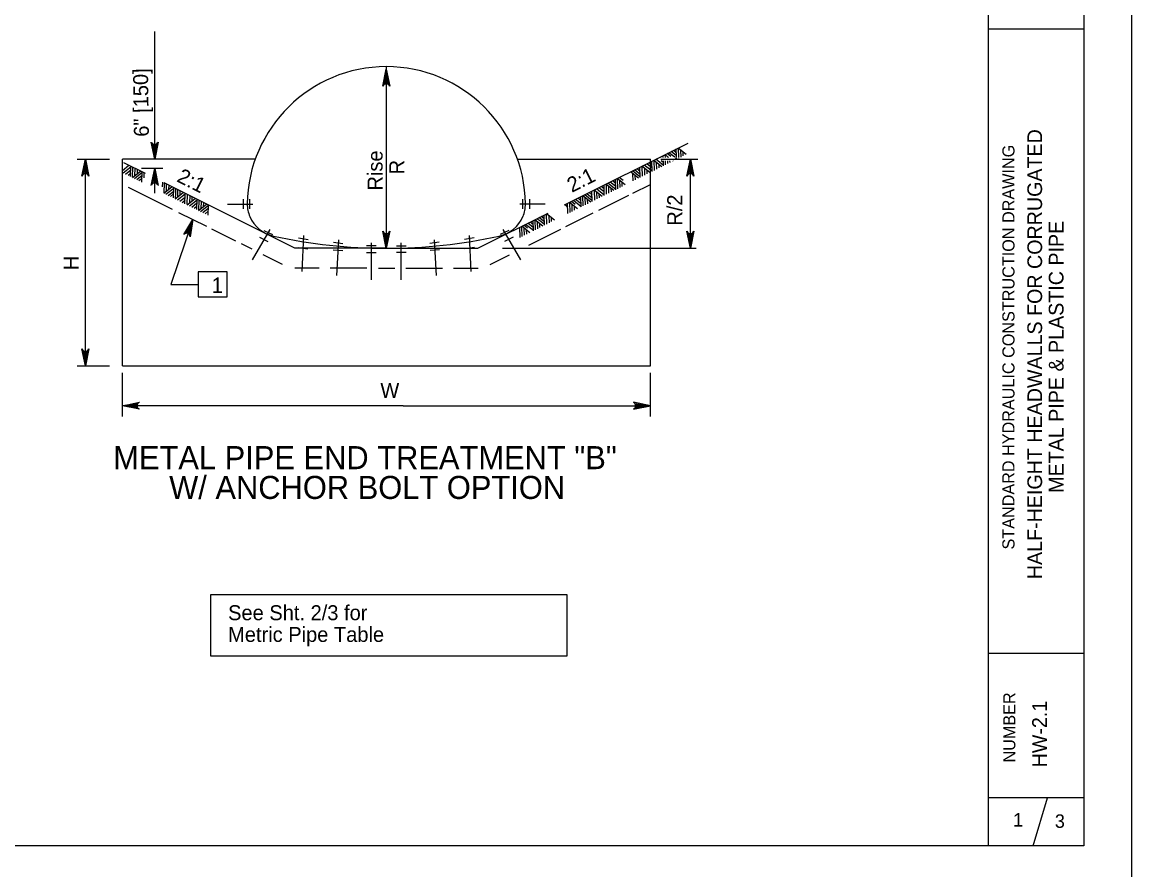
# Model space of a CAD drawing. Extents: x 1083.1 to 1117.1, y 675.4 to 741.4.
# Drawn here: x 1105.58 to 1117.13, y 719.6 to 728.43 of the extents above; entities that cross this region are included whole.
import ezdxf

# ---------------------------------------------------------------- set-up
doc = ezdxf.new("R2010")
doc.units = 0
doc.layers.add('Level 1', color=7, linetype='Continuous')

msp = doc.modelspace()

# ---------------------------------------------------------------- linework, layer by layer
at = {"layer": 'Level 1'}
for p, q in [((1115.636, 719.854), (1115.636, 740.854)), ((1106.962, 727.001), (1106.962, 728.328)), ((1116.626, 728.354), (1115.636, 728.354)), ((1109.347, 727.775), (1109.371, 727.937)), ((1109.357, 727.781), (1109.371, 727.937)), ((1109.371, 727.964), (1109.371, 726.643)), ((1109.371, 727.784), (1109.371, 727.937)), ((1109.383, 727.782), (1109.371, 727.937)), ((1109.394, 727.777), (1109.371, 727.937)), ((1106.939, 727.161), (1106.962, 727.001)), ((1106.95, 727.156), (1106.962, 727.001)), ((1106.987, 727.163), (1106.962, 727.001)), ((1106.976, 727.157), (1106.962, 727.001)), ((1106.962, 727.154), (1106.962, 727.001)), ((1111.223, 726.524), (1112.512, 727.168)), ((1112.229, 727.017), (1112.222, 727.023)), ((1112.252, 727.017), (1112.251, 727.038)), ((1112.307, 727.019), (1112.271, 727.048)), ((1112.274, 727.018), (1112.273, 727.045)), ((1112.331, 727.027), (1112.292, 727.058)), ((1112.298, 727.018), (1112.297, 727.026)), ((1112.371, 727.02), (1112.311, 727.067)), ((1112.391, 727.034), (1112.334, 727.079)), ((1112.39, 727.066), (1112.359, 727.091)), ((1112.392, 727.003), (1112.378, 727.014)), ((1112.391, 727.02), (1112.388, 727.107)), ((1112.392, 727), (1112.391, 727.015)), ((1112.491, 727.049), (1112.408, 727.116)), ((1112.413, 727.02), (1112.41, 727.114)), ((1112.413, 727.01), (1112.413, 727.016)), ((1112.437, 727.022), (1112.434, 727.095)), ((1112.46, 727.034), (1112.458, 727.076)), ((1106.154, 727.001), (1106.493, 727.001)), ((1106.215, 726.839), (1106.24, 727.001)), ((1106.226, 726.845), (1106.24, 727.001)), ((1106.24, 725.784), (1106.24, 727.001)), ((1106.24, 726.848), (1106.24, 727.001)), ((1106.251, 726.846), (1106.24, 727.001)), ((1106.262, 726.841), (1106.24, 727.001)), ((1106.625, 724.848), (1106.625, 727.001)), ((1108.008, 727.001), (1106.625, 727.001)), ((1106.625, 726.881), (1106.694, 726.937)), ((1106.634, 726.858), (1106.714, 726.921)), ((1106.866, 726.851), (1106.641, 726.963)), ((1106.659, 726.846), (1106.713, 726.889)), ((1106.711, 726.82), (1106.714, 726.926)), ((1106.732, 726.812), (1106.735, 726.916)), ((1106.756, 726.832), (1106.758, 726.904)), ((1106.781, 726.852), (1106.783, 726.892)), ((1107.045, 726.905), (1106.823, 726.905)), ((1106.937, 726.743), (1106.962, 726.905)), ((1106.947, 726.749), (1106.962, 726.905)), ((1106.962, 726.647), (1106.962, 726.905)), ((1106.962, 726.752), (1106.962, 726.905)), ((1106.973, 726.75), (1106.962, 726.905)), ((1106.984, 726.745), (1106.962, 726.905)), ((1110.735, 727.001), (1112.118, 727.001)), ((1112.01, 726.844), (1111.954, 726.889)), ((1112.009, 726.875), (1111.977, 726.901)), ((1112.011, 726.809), (1112.007, 726.916)), ((1112.113, 726.861), (1112.03, 726.927)), ((1112.036, 726.822), (1112.034, 726.924)), ((1112.136, 726.875), (1112.055, 726.939)), ((1112.061, 726.834), (1112.059, 726.904)), ((1112.135, 726.908), (1112.08, 726.952)), ((1112.133, 726.939), (1112.103, 726.963)), ((1112.118, 724.848), (1112.118, 727.001)), ((1112.136, 726.872), (1112.133, 726.978)), ((1112.236, 726.922), (1112.153, 726.988)), ((1112.16, 726.884), (1112.157, 726.985)), ((1112.194, 726.983), (1112.174, 726.999)), ((1112.185, 726.896), (1112.182, 726.965)), ((1112.255, 726.935), (1112.195, 726.982)), ((1112.21, 726.909), (1112.208, 726.944)), ((1112.226, 727.001), (1112.612, 727.001)), ((1112.254, 726.965), (1112.23, 726.984)), ((1112.255, 726.931), (1112.253, 726.984)), ((1112.276, 726.942), (1112.275, 726.983)), ((1112.3, 726.954), (1112.299, 726.983)), ((1112.323, 726.965), (1112.322, 726.983)), ((1112.354, 726.981), (1112.352, 726.982)), ((1112.509, 726.839), (1112.534, 727.001)), ((1112.519, 726.845), (1112.534, 727.001)), ((1112.534, 726.373), (1112.534, 727.001)), ((1112.534, 726.848), (1112.534, 727.001)), ((1112.545, 726.846), (1112.534, 727.001)), ((1112.556, 726.841), (1112.534, 727.001)), ((1106.684, 726.833), (1106.712, 726.856)), ((1106.729, 726.811), (1106.813, 726.877)), ((1106.751, 726.8), (1106.832, 726.864)), ((1106.775, 726.788), (1106.831, 726.833)), ((1106.797, 726.777), (1106.83, 726.803)), ((1106.829, 726.761), (1106.832, 726.867)), ((1106.852, 726.807), (1106.853, 726.857)), ((1111.756, 726.749), (1111.724, 726.774)), ((1111.758, 726.683), (1111.754, 726.79)), ((1111.857, 726.732), (1111.774, 726.799)), ((1111.779, 726.693), (1111.776, 726.797)), ((1111.834, 726.779), (1111.795, 726.81)), ((1111.803, 726.705), (1111.8, 726.778)), ((1111.994, 726.801), (1111.911, 726.867)), ((1111.971, 726.847), (1111.932, 726.878)), ((1111.94, 726.774), (1111.937, 726.846)), ((1111.963, 726.785), (1111.961, 726.827)), ((1112.01, 726.816), (1111.971, 726.847)), ((1112.086, 726.847), (1112.084, 726.883)), ((1107.147, 726.477), (1106.689, 726.706)), ((1107.043, 726.712), (1107.045, 726.761)), ((1107.057, 726.647), (1107.141, 726.713)), ((1108.42, 726.073), (1107.06, 726.753)), ((1107.06, 726.649), (1107.063, 726.752)), ((1107.079, 726.636), (1107.159, 726.7)), ((1107.084, 726.668), (1107.086, 726.74)), ((1107.103, 726.624), (1107.159, 726.669)), ((1107.109, 726.688), (1107.111, 726.728)), ((1107.157, 726.597), (1107.16, 726.703)), ((1107.18, 726.643), (1107.182, 726.693)), ((1107.201, 726.61), (1107.203, 726.682)), ((1107.225, 726.63), (1107.226, 726.67)), ((1111.514, 726.561), (1111.51, 726.667)), ((1111.616, 726.612), (1111.533, 726.678)), ((1111.539, 726.574), (1111.537, 726.675)), ((1111.639, 726.626), (1111.558, 726.691)), ((1111.638, 726.659), (1111.583, 726.703)), ((1111.636, 726.69), (1111.606, 726.715)), ((1111.639, 726.623), (1111.636, 726.73)), ((1111.739, 726.674), (1111.656, 726.74)), ((1111.663, 726.635), (1111.66, 726.737)), ((1111.758, 726.686), (1111.677, 726.75)), ((1111.687, 726.648), (1111.685, 726.717)), ((1111.757, 726.717), (1111.7, 726.762)), ((1111.713, 726.66), (1111.711, 726.696)), ((1111.826, 726.717), (1111.824, 726.759)), ((1111.935, 726.646), (1112.118, 726.738)), ((1107.125, 726.613), (1107.158, 726.639)), ((1107.173, 726.589), (1107.257, 726.655)), ((1107.179, 726.593), (1107.18, 726.643)), ((1107.199, 726.576), (1107.279, 726.639)), ((1107.224, 726.563), (1107.278, 726.606)), ((1107.248, 726.551), (1107.277, 726.574)), ((1107.276, 726.537), (1107.279, 726.644)), ((1107.299, 726.526), (1107.382, 726.592)), ((1107.301, 726.528), (1107.304, 726.631)), ((1107.322, 726.514), (1107.402, 726.577)), ((1107.327, 726.548), (1107.329, 726.619)), ((1107.347, 726.502), (1107.401, 726.545)), ((1107.351, 726.568), (1107.352, 726.607)), ((1107.399, 726.476), (1107.402, 726.582)), ((1107.42, 726.468), (1107.423, 726.572)), ((1107.444, 726.488), (1107.447, 726.56)), ((1107.469, 726.508), (1107.471, 726.548)), ((1107.882, 726.583), (1107.882, 726.483)), ((1107.951, 726.483), (1107.951, 726.583)), ((1109.371, 726.653), (1109.371, 726.073)), ((1110.792, 726.483), (1110.792, 726.583)), ((1110.861, 726.583), (1110.861, 726.483)), ((1111.261, 726.434), (1111.257, 726.541)), ((1111.36, 726.484), (1111.277, 726.55)), ((1111.282, 726.445), (1111.279, 726.548)), ((1111.337, 726.53), (1111.298, 726.561)), ((1111.398, 726.506), (1111.317, 726.57)), ((1111.397, 726.537), (1111.34, 726.582)), ((1111.396, 726.569), (1111.364, 726.594)), ((1111.398, 726.503), (1111.394, 726.61)), ((1111.497, 726.552), (1111.414, 726.619)), ((1111.419, 726.514), (1111.416, 726.617)), ((1111.474, 726.599), (1111.435, 726.63)), ((1111.443, 726.525), (1111.44, 726.597)), ((1111.513, 726.596), (1111.456, 726.64)), ((1111.466, 726.537), (1111.464, 726.579)), ((1111.513, 726.567), (1111.474, 726.599)), ((1111.512, 726.627), (1111.48, 726.652)), ((1111.564, 726.586), (1111.562, 726.655)), ((1111.582, 726.47), (1111.893, 726.625)), ((1111.589, 726.598), (1111.587, 726.635)), ((1107.503, 726.299), (1107.214, 726.443)), ((1107.372, 726.489), (1107.4, 726.511)), ((1107.418, 726.466), (1107.501, 726.533)), ((1107.439, 726.456), (1107.52, 726.52)), ((1107.463, 726.444), (1107.519, 726.489)), ((1107.486, 726.433), (1107.518, 726.459)), ((1107.517, 726.417), (1107.52, 726.523)), ((1107.718, 726.533), (1107.982, 726.533)), ((1110.323, 726.073), (1111.056, 726.44)), ((1111.025, 726.533), (1110.76, 726.533)), ((1111.119, 726.364), (1111.036, 726.43)), ((1111.042, 726.325), (1111.039, 726.427)), ((1111.259, 726.501), (1111.227, 726.526)), ((1111.239, 726.299), (1111.523, 726.441)), ((1111.306, 726.457), (1111.303, 726.529)), ((1111.329, 726.468), (1111.327, 726.51)), ((1107.28, 726.227), (1107.359, 726.371)), ((1107.292, 726.229), (1107.359, 726.371)), ((1107.307, 726.227), (1107.359, 726.371)), ((1107.317, 726.222), (1107.359, 726.371)), ((1107.325, 726.213), (1107.359, 726.371)), ((1110.84, 726.282), (1110.801, 726.313)), ((1110.901, 726.258), (1110.82, 726.322)), ((1110.9, 726.288), (1110.843, 726.334)), ((1110.899, 726.32), (1110.867, 726.346)), ((1110.901, 726.254), (1110.897, 726.361)), ((1111, 726.304), (1110.917, 726.37)), ((1110.922, 726.265), (1110.919, 726.368)), ((1110.977, 726.35), (1110.938, 726.381)), ((1110.946, 726.277), (1110.943, 726.349)), ((1111.015, 726.347), (1110.959, 726.392)), ((1110.968, 726.288), (1110.967, 726.33)), ((1111.016, 726.319), (1110.977, 726.35)), ((1111.014, 726.378), (1110.983, 726.404)), ((1111.016, 726.312), (1111.013, 726.419)), ((1111.067, 726.337), (1111.065, 726.407)), ((1111.091, 726.35), (1111.09, 726.386)), ((1112.534, 726.073), (1112.534, 726.373)), ((1107.807, 726.147), (1107.556, 726.272)), ((1108.16, 726.269), (1107.976, 725.952)), ((1108.096, 726.257), (1108.188, 726.217)), ((1108.51, 726.206), (1108.492, 725.833)), ((1109.349, 726.234), (1109.371, 726.073)), ((1109.36, 726.228), (1109.371, 726.073)), ((1109.396, 726.236), (1109.371, 726.073)), ((1109.386, 726.23), (1109.371, 726.073)), ((1109.371, 726.227), (1109.371, 726.073)), ((1110.233, 726.206), (1110.251, 725.833)), ((1110.646, 726.257), (1110.555, 726.217)), ((1110.583, 726.269), (1110.767, 725.952)), ((1110.764, 726.186), (1110.76, 726.293)), ((1110.863, 726.235), (1110.78, 726.302)), ((1110.785, 726.197), (1110.782, 726.3)), ((1110.809, 726.208), (1110.806, 726.281)), ((1110.832, 726.22), (1110.83, 726.262)), ((1110.855, 726.107), (1111.187, 726.272)), ((1112.512, 726.234), (1112.534, 726.073)), ((1112.523, 726.228), (1112.534, 726.073)), ((1112.559, 726.236), (1112.534, 726.073)), ((1112.548, 726.23), (1112.534, 726.073)), ((1112.534, 726.227), (1112.534, 726.073)), ((1107.976, 726.063), (1107.863, 726.119)), ((1108.051, 726.188), (1108.14, 726.144)), ((1108.455, 726.081), (1108.554, 726.066)), ((1108.459, 726.182), (1108.557, 726.166)), ((1108.822, 726.138), (1108.92, 726.122)), ((1108.872, 726.162), (1108.854, 725.789)), ((1109.266, 726.098), (1109.166, 726.098)), ((1109.216, 725.745), (1109.216, 726.13)), ((1109.477, 726.098), (1109.577, 726.098)), ((1109.527, 725.745), (1109.527, 726.13)), ((1109.921, 726.138), (1109.823, 726.122)), ((1109.87, 726.162), (1109.888, 725.789)), ((1110.284, 726.182), (1110.185, 726.166)), ((1110.288, 726.081), (1110.189, 726.066)), ((1110.692, 726.188), (1110.602, 726.144)), ((1108.291, 725.905), (1108.089, 726.006)), ((1109.378, 726.073), (1108.42, 726.073)), ((1108.817, 726.058), (1108.917, 726.051)), ((1109.166, 726.029), (1109.266, 726.029)), ((1109.378, 726.073), (1110.323, 726.073)), ((1109.577, 726.029), (1109.477, 726.029)), ((1109.926, 726.058), (1109.826, 726.051)), ((1110.452, 725.905), (1110.654, 726.006)), ((1110.581, 726.073), (1112.593, 726.073)), ((1108.674, 725.865), (1108.418, 725.865)), ((1109.168, 725.865), (1108.788, 725.865)), ((1109.29, 725.865), (1109.458, 725.865)), ((1109.575, 725.865), (1109.954, 725.865)), ((1110.069, 725.865), (1110.325, 725.865)), ((1106.24, 724.848), (1106.24, 725.784)), ((1107.415, 725.828), (1107.415, 725.567)), ((1107.714, 725.828), (1107.415, 725.828)), ((1107.714, 725.567), (1107.714, 725.828)), ((1107.415, 725.567), (1107.714, 725.567)), ((1115.868, 725.06), (1115.868, 725.06)), ((1116.258, 725.067), (1116.258, 725.067)), ((1106.218, 725.009), (1106.24, 724.848)), ((1106.229, 725.003), (1106.24, 724.848)), ((1106.265, 725.011), (1106.24, 724.848)), ((1106.254, 725.005), (1106.24, 724.848)), ((1106.24, 725.002), (1106.24, 724.848)), ((1106.154, 724.848), (1106.493, 724.848)), ((1106.625, 724.848), (1112.118, 724.848)), ((1106.622, 724.778), (1106.622, 724.323)), ((1112.115, 724.778), (1112.115, 724.323)), ((1106.785, 724.457), (1106.625, 724.434)), ((1106.779, 724.446), (1106.625, 724.434)), ((1109.547, 724.434), (1106.625, 724.434)), ((1106.778, 724.434), (1106.625, 724.434)), ((1106.781, 724.42), (1106.625, 724.434)), ((1106.787, 724.41), (1106.625, 724.434)), ((1109.547, 724.434), (1112.118, 724.434)), ((1111.956, 724.41), (1112.118, 724.434)), ((1111.958, 724.457), (1112.118, 724.434)), ((1111.962, 724.42), (1112.118, 724.434)), ((1111.963, 724.446), (1112.118, 724.434)), ((1111.965, 724.434), (1112.118, 724.434)), ((1107.544, 722.47), (1111.249, 722.47)), ((1107.544, 721.828), (1107.544, 722.47)), ((1111.249, 722.47), (1111.249, 721.828)), ((1111.249, 721.828), (1107.544, 721.828)), ((1116.626, 721.854), (1115.636, 721.854)), ((1116.626, 720.354), (1115.636, 720.354)), ((1116.101, 719.854), (1116.251, 720.354))]:
    msp.add_line(p, q, dxfattribs=at)
for points in [[(1083.126, 719.354), (1117.126, 719.354), (1117.126, 741.354), (1083.126, 741.354)], [(1085.126, 740.854), (1116.626, 740.854), (1116.626, 719.854), (1085.126, 719.854)]]:
    msp.add_lwpolyline(points, close=True, dxfattribs=at)
for points in [[(1109.336, 727.76), (1109.371, 727.937), (1109.407, 727.76)], [(1106.997, 727.178), (1106.962, 727.001), (1106.926, 727.178)], [(1106.205, 726.824), (1106.24, 727.001), (1106.275, 726.824)], [(1106.926, 726.728), (1106.962, 726.905), (1106.997, 726.728)], [(1112.498, 726.824), (1112.534, 727.001), (1112.569, 726.824)], [(1107.359, 726.371), (1107.131, 725.697), (1107.415, 725.697)], [(1107.265, 726.217), (1107.359, 726.371), (1107.332, 726.193)], [(1109.407, 726.25), (1109.371, 726.073), (1109.336, 726.25)], [(1112.569, 726.25), (1112.534, 726.073), (1112.498, 726.25)], [(1106.275, 725.025), (1106.24, 724.848), (1106.205, 725.025)], [(1106.802, 724.399), (1106.625, 724.434), (1106.802, 724.47)], [(1111.941, 724.399), (1112.118, 724.434), (1111.941, 724.47)]]:
    msp.add_lwpolyline(points, dxfattribs=at)
for centre, start, end in [((1109.371, 727.746), 22.0878, 157.9139), ((1106.962, 727.193), 202.0878, 337.9139), ((1106.24, 726.81), 22.0878, 157.9139), ((1112.534, 726.81), 22.0878, 157.9139), ((1106.962, 726.714), 22.0878, 157.9139), ((1107.294, 726.191), 2.2124, 138.0385), ((1109.371, 726.265), 202.0878, 337.9139), ((1112.534, 726.265), 202.0878, 337.9139), ((1106.24, 725.04), 202.0878, 337.9139), ((1106.816, 724.434), 112.0878, 247.9139), ((1111.927, 724.434), 292.0861, 67.9122)]:
    msp.add_arc(centre, 0.0382, start, end, dxfattribs=at)
for centre, major_axis, start_param, end_param in [((1109.376, 726.511), (-1.453, 0), 4.71537, 6.266539), ((1109.367, 726.511), (1.453, 0), 0.016646, 1.567816), ((1108.37, 726.559), (-0.448, 0), 0.055055, 0.354919), ((1110.373, 726.559), (0.448, 0), 5.928267, 6.22813), ((1108.272, 726.542), (-0.35, 0), 0.40505, 1.357703), ((1110.471, 726.542), (0.35, 0), 4.925482, 5.878135), ((1109.36, 731.492), (5.419, 0), 4.496144, 4.714418), ((1109.383, 731.492), (-5.419, 0), 1.568767, 1.787041)]:
    msp.add_ellipse(centre, major_axis=major_axis, ratio=0.999895, start_param=start_param, end_param=end_param, dxfattribs=at)

# ---------------------------------------------------------------- texts
for s, height, rotation, p in [('6" [150]', 0.156, 90.8499, (1106.902, 727.235)), ('HALF-HEIGHT HEADWALLS FOR CORRUGATED', 0.153, 90, (1116.193, 722.629)), ('STANDARD HYDRAULIC CONSTRUCTION DRAWING', 0.126, 90, (1115.906, 722.938)), ('Rise', 0.156, 90, (1109.332, 726.674)), ('2:1', 0.156, 333.4374, (1107.181, 726.772)), ('R', 0.156, 90, (1109.558, 726.842)), ('2:1', 0.156, 26.5626, (1111.301, 726.65)), ('R/2', 0.156, 90, (1112.449, 726.308)), ('METAL PIPE & PLASTIC PIPE', 0.153, 90, (1116.416, 723.528)), ('H', 0.156, 90, (1106.169, 725.844)), ('See Sht. 2/3 for ', 0.156, 0, (1107.725, 722.202)), ('Metric Pipe Table', 0.156, 0, (1107.725, 721.976)), ('NUMBER', 0.126, 90, (1115.915, 720.721)), ('HW-2.1', 0.153, 90, (1116.243, 720.67))]:
    msp.add_text(s, height=height, rotation=rotation, dxfattribs=at).set_placement(p)
for s, height, p in [('1', 0.16, (1107.554, 725.609)), ('W', 0.156, (1109.309, 724.516)), ('METAL PIPE END TREATMENT "B"', 0.24, (1106.53, 723.774)), ('W/ ANCHOR BOLT OPTION', 0.24, (1107.112, 723.464)), ('1', 0.14, (1115.891, 720.054)), ('3', 0.14, (1116.326, 720.041))]:
    msp.add_text(s, height=height, dxfattribs=at).set_placement(p)

doc.saveas('drawing.dxf')
